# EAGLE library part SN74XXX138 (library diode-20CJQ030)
TI's SN74xxx138 3-Line to 8-Line Decoder/DemultiplexerDescription: The HC138 devices are designed to be used in high-performance memory-decoding or datarouting applications requiring very short propagation delay times. In high-performance memory systems, these decoders can be used to minimize the effects of system decoding. When employed with high-speed memories utilizing a fast enable circuit, the delay times of these decoders and the enable time of the memory are usually less than the typical access time of the memory. This means that the effective system delay introduced by the decoders is negligible. Features: Targeted Specifically for High-Speed Memory Decoders and Data-Transmission Systems Wide Operating Voltage Range of 2 V to 6 V Outputs Can Drive Up To 10 LSTTL Loads Low Power Consumption, 80-µA Max ICC Typical tpd = 15 ns ±4-mA Output Drive at 5 V Low Input Current of 1 µA Max Incorporate Three Enable Inputs to SimplifyCascading and/or Data Reception Please send any comments to: messi@users.sourceforge.net
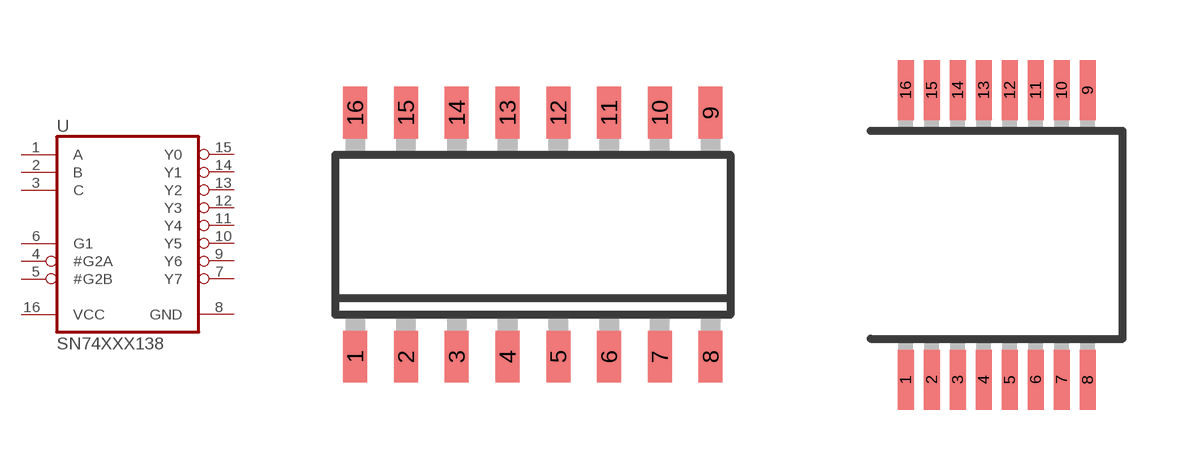
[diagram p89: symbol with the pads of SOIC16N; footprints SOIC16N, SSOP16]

Designator prefix U

## SN74XXX138D  [SOIC16N]
1  A  in
2  B  in
3  C  in
4  #G2A  in
5  #G2B  in
6  G1  in
7  Y7  out
8  GND  pwr
9  Y6  out
10  Y5  out
11  Y4  out
12  Y3  out
13  Y2  out
14  Y1  out
15  Y0  out
16  VCC  pwr

## SN74XXX138DB  [SSOP16]
Pads as for SOIC16N

## SN74XXX138PW  [TSSOP16]
Pads as for SOIC16N

## SN74XXX138-RGY  [QFN-16W]
Pads as for SOIC16N

## Footprint SOIC16N (pad centres in mm)
SMALL OUTLINE INTEGRATED CIRCUIT
smd 0.6 x 1.3: 1 -4.445,-3.05; 2 -3.175,-3.05; 3 -1.905,-3.05; 4 -0.635,-3.05; 5 0.635,-3.05; 6 1.905,-3.05; 7 3.175,-3.05; 8 4.445,-3.05; 9 4.445,3.05; 10 3.175,3.05; 11 1.905,3.05; 12 0.635,3.05; 13 -0.635,3.05; 14 -1.905,3.05; 15 -3.175,3.05; 16 -4.445,3.05

## Footprint SSOP16 (pad centres in mm)
Shrink Small Outline Package package type SS
smd 0.4 x 1.5: 1 -2.275,-3.625; 2 -1.625,-3.625; 3 -0.975,-3.625; 4 -0.325,-3.625; 5 0.325,-3.625; 6 0.975,-3.625; 7 1.625,-3.625; 8 2.275,-3.625; 9 2.275,3.625; 10 1.625,3.625; 11 0.975,3.625; 12 0.325,3.625; 13 -0.325,3.625; 14 -0.975,3.625; 15 -1.625,3.625; 16 -2.275,3.625

## Footprint TSSOP16 (pad centres in mm)
Thin Shrink Small Outline Plastic 16 MAX3223-MAX3243.pdf
smd 0.305 x 0.991: 1 -2.275,-2.918; 2 -1.625,-2.918; 3 -0.975,-2.918; 4 -0.325,-2.918; 5 0.325,-2.918; 6 0.975,-2.918; 7 1.625,-2.918; 8 2.275,-2.918; 9 2.275,2.918; 10 1.625,2.918; 11 0.975,2.918; 12 0.325,2.918; 13 -0.325,2.918; 14 -0.975,2.918; 15 -1.625,2.918; 16 -2.275,2.918

## Footprint QFN-16W (pad centres in mm)
smd 0.55 x 0.35: 1 -1.9,-0.75; 8 1.9,-0.75; 9 1.9,0.75; 16 -1.9,0.75
smd 0.35 x 0.55: 2 -1.25,-1.65; 3 -0.75,-1.65; 4 -0.25,-1.65; 5 0.25,-1.65; 6 0.75,-1.65; 7 1.25,-1.65; 10 1.25,1.65; 11 0.75,1.65; 12 0.25,1.65; 13 -0.25,1.65; 14 -0.75,1.65; 15 -1.25,1.65
smd 2.6 x 2.1: P$1 0,0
